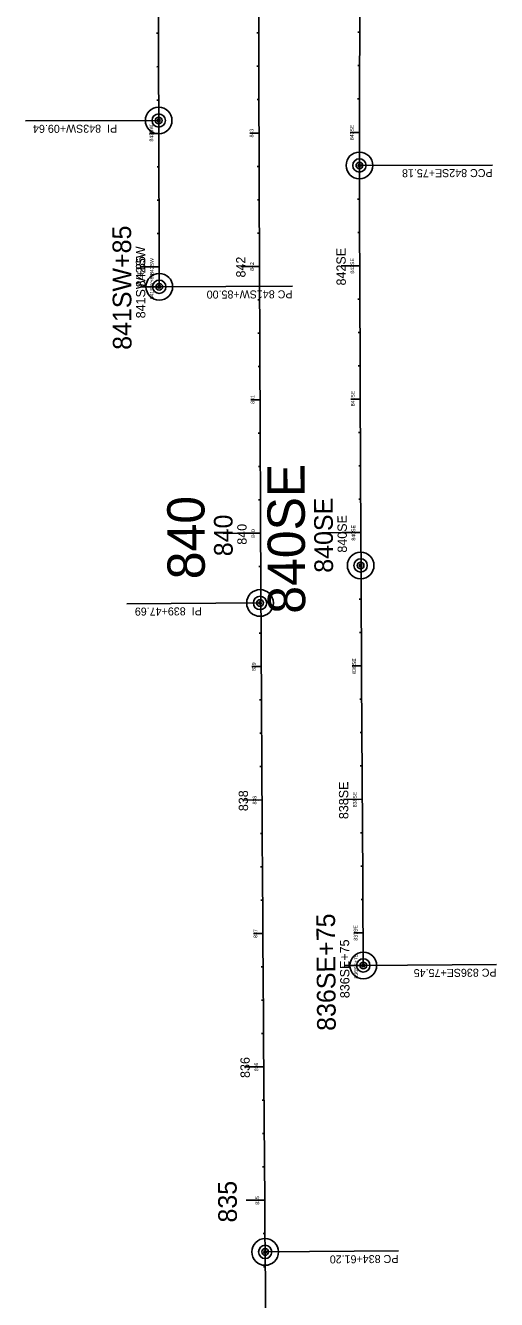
# Model space of a CAD drawing. Extents: x 536709 to 765910, y 180209 to 191282.
# Drawn here: x 593844 to 594197, y 182695 to 183650 of the extents above; entities that cross this region are included whole.
import ezdxf

# ---------------------------------------------------------------- set-up
doc = ezdxf.new("R2010")
doc.units = 0
for name, color, linetype in [('P_ALI_100', 7, 'Continuous'), ('P_ALI_100_Sta', 7, 'Continuous'), ('P_ALI_100_Tic', 7, 'Continuous'), ('P_ALI_100_TPI', 7, 'Continuous'), ('P_ALI_20', 7, 'Continuous'), ('P_ALI_200', 7, 'Continuous'), ('P_ALI_200_Sta', 7, 'Continuous'), ('P_ALI_200_Tic', 7, 'Continuous'), ('P_ALI_200_TPI', 7, 'Continuous'), ('P_ALI_20_Sta', 7, 'Continuous'), ('P_ALI_20_Tic', 7, 'Continuous'), ('P_ALI_20_TPI', 7, 'Continuous'), ('P_ALI_50', 7, 'Continuous'), ('P_ALI_50_CPIData', 7, 'Continuous'), ('P_ALI_50_PIData', 7, 'Continuous'), ('P_ALI_50_Sta', 7, 'Continuous'), ('P_ALI_50_Tic', 7, 'Continuous'), ('P_ALI_50_TPI', 7, 'Continuous')]:
    doc.layers.add(name, color=color, linetype=linetype)

msp = doc.modelspace()

# ---------------------------------------------------------------- linework, layer by layer
at = {"layer": 'P_ALI_100'}
msp.add_line((594043.57, 180219.08), (594023.71, 182730.2), dxfattribs=at)
for centre, radius, start, end in [((602094.41, 183570.03), 8000, 177.280358, 180.181641), ((765899.68, 184089.33), 171956.59, 180.1287302, 180.211791), ((765899.68, 184089.33), 171881.34, 180.1287302, 180.4530652), ((765899.68, 184089.33), 171806.09, 180.1816411, 180.381647)]:
    msp.add_arc(centre, radius, start, end, dxfattribs=at)
at = {"layer": 'P_ALI_100_Tic'}
for points in [[(594012.13, 183568.96), (594019.13, 183568.98)], [(594087.41, 183569.48), (594094.41, 183569.48)], [(593936.88, 183568.68), (593943.88, 183568.71)], [(593937.21, 183468.68), (593944.21, 183468.71)], [(594012.46, 183468.96), (594019.46, 183468.98)], [(594087.71, 183469.46), (594094.71, 183469.49)], [(593930.26, 183453.65), (593944.26, 183453.71)], [(593937.26, 183453.68), (593944.26, 183453.71)], [(594012.85, 183368.96), (594019.85, 183368.98)], [(594088.1, 183369.46), (594095.1, 183369.49)], [(594006.3, 183268.92), (594020.3, 183268.99)], [(594081.55, 183269.42), (594095.54, 183269.49)], [(594013.8, 183168.95), (594020.8, 183168.99)], [(594089.05, 183169.45), (594096.05, 183169.49)], [(594014.37, 183068.95), (594021.37, 183068.99)], [(594089.62, 183069.45), (594096.62, 183069.49)], [(594014.99, 182968.95), (594021.99, 182968.99)], [(594090.24, 182969.45), (594097.24, 182969.49)], [(594083.4, 182944.85), (594097.4, 182944.94)], [(594090.4, 182944.9), (594097.4, 182944.94)], [(594015.67, 182868.94), (594022.67, 182868.99)], [(594009.41, 182768.89), (594023.41, 182769)]]:
    msp.add_lwpolyline(points, dxfattribs=at)
at = {"layer": 'P_ALI_100_TPI'}
for centre in [(593943.8, 183578.35), (594094.45, 183544.67), (593944.26, 183453.71), (594095.4, 183244.8), (594019.87, 183216.67), (594097.4, 182944.94), (594023.71, 182730.2)]:
    msp.add_circle(centre, 5, dxfattribs=at)
at = {"layer": 'P_ALI_20'}
msp.add_line((594043.57, 180219.08), (594023.71, 182730.2), dxfattribs=at)
for centre, radius, start, end in [((602094.41, 183570.03), 8000, 177.280358, 180.181641), ((765899.68, 184089.33), 171956.59, 180.1287302, 180.211791), ((765899.68, 184089.33), 171881.34, 180.1287302, 180.4530652), ((765899.68, 184089.33), 171806.09, 180.1816411, 180.381647)]:
    msp.add_arc(centre, radius, start, end, dxfattribs=at)
at = {"layer": 'P_ALI_200'}
msp.add_line((594043.57, 180219.08), (594023.71, 182730.2), dxfattribs=at)
for centre, radius, start, end in [((602094.41, 183570.03), 8000, 177.280358, 180.181641), ((765899.68, 184089.33), 171956.59, 180.1287302, 180.211791), ((765899.68, 184089.33), 171881.34, 180.1287302, 180.4530652), ((765899.68, 184089.33), 171806.09, 180.1816411, 180.381647)]:
    msp.add_arc(centre, radius, start, end, dxfattribs=at)
at = {"layer": 'P_ALI_200_Tic'}
for points in [[(593930.21, 183468.66), (593944.21, 183468.71)], [(594005.46, 183468.93), (594019.46, 183468.98)], [(594080.71, 183469.43), (594094.71, 183469.49)], [(593992.3, 183268.85), (594020.3, 183268.99)], [(594067.55, 183269.35), (594095.54, 183269.49)], [(594007.37, 183068.91), (594021.37, 183068.99)], [(594082.62, 183069.41), (594096.62, 183069.49)], [(594008.67, 182868.89), (594022.67, 182868.99)]]:
    msp.add_lwpolyline(points, dxfattribs=at)
at = {"layer": 'P_ALI_200_TPI'}
for centre in [(593943.8, 183578.35), (594094.45, 183544.67), (593944.26, 183453.71), (594095.4, 183244.8), (594019.87, 183216.67), (594097.4, 182944.94), (594023.71, 182730.2)]:
    msp.add_circle(centre, 10, dxfattribs=at)
at = {"layer": 'P_ALI_20_Tic'}
for points in [[(593942.27, 183643.7), (593943.67, 183643.71)], [(594017.52, 183643.98), (594018.92, 183643.98)], [(594093.36, 183644.5), (594094.76, 183644.48)], [(593942.33, 183618.7), (593943.73, 183618.71)], [(594017.58, 183618.98), (594018.98, 183618.98)], [(594093.16, 183619.49), (594094.56, 183619.48)], [(593942.4, 183593.7), (593943.8, 183593.71)], [(594017.65, 183593.98), (594019.05, 183593.98)], [(594093.05, 183594.49), (594094.45, 183594.48)], [(594016.33, 183568.98), (594019.13, 183568.98)], [(594091.61, 183569.48), (594094.41, 183569.48)], [(593941.08, 183568.7), (593943.88, 183568.71)], [(593942.55, 183543.7), (593943.95, 183543.71)], [(594017.8, 183543.98), (594019.2, 183543.98)], [(594093.05, 183544.48), (594094.45, 183544.48)], [(593942.64, 183518.7), (593944.04, 183518.71)], [(594017.89, 183518.98), (594019.29, 183518.98)], [(594093.13, 183519.48), (594094.53, 183519.49)], [(593942.72, 183493.7), (593944.12, 183493.71)], [(594017.97, 183493.98), (594019.37, 183493.98)], [(594093.22, 183494.48), (594094.62, 183494.49)], [(593941.41, 183468.7), (593944.21, 183468.71)], [(594016.66, 183468.97), (594019.46, 183468.98)], [(594091.91, 183469.48), (594094.71, 183469.49)], [(593941.46, 183453.7), (593944.26, 183453.71)], [(593942.86, 183453.7), (593944.26, 183453.71)], [(594018.15, 183443.98), (594019.55, 183443.98)], [(594093.4, 183444.48), (594094.8, 183444.49)], [(594018.25, 183418.98), (594019.65, 183418.98)], [(594093.49, 183419.48), (594094.89, 183419.49)], [(594018.35, 183393.98), (594019.75, 183393.98)], [(594093.59, 183394.48), (594094.99, 183394.49)], [(594017.05, 183368.97), (594019.85, 183368.98)], [(594092.3, 183369.47), (594095.1, 183369.49)], [(594018.55, 183343.98), (594019.95, 183343.99)], [(594093.8, 183344.48), (594095.2, 183344.49)], [(594018.67, 183318.98), (594020.07, 183318.99)], [(594093.91, 183319.48), (594095.31, 183319.49)], [(594018.78, 183293.98), (594020.18, 183293.99)], [(594094.03, 183294.48), (594095.43, 183294.49)], [(594017.5, 183268.97), (594020.3, 183268.99)], [(594092.74, 183269.47), (594095.54, 183269.49)], [(594094.27, 183244.48), (594095.67, 183244.49)], [(594019.02, 183243.98), (594020.42, 183243.99)], [(594019.14, 183218.98), (594020.54, 183218.99)], [(594094.39, 183219.48), (594095.79, 183219.49)], [(594019.27, 183193.98), (594020.67, 183193.99)], [(594094.52, 183194.48), (594095.92, 183194.49)], [(594018, 183168.97), (594020.8, 183168.99)], [(594093.25, 183169.47), (594096.05, 183169.49)], [(594019.54, 183143.98), (594020.94, 183143.99)], [(594094.79, 183144.48), (594096.19, 183144.49)], [(594019.68, 183118.98), (594021.08, 183118.99)], [(594094.93, 183119.48), (594096.33, 183119.49)], [(594019.82, 183093.98), (594021.22, 183093.99)], [(594095.07, 183094.48), (594096.47, 183094.49)], [(594018.57, 183068.97), (594021.37, 183068.99)], [(594093.82, 183069.47), (594096.62, 183069.49)], [(594020.12, 183043.98), (594021.52, 183043.99)], [(594095.37, 183044.48), (594096.77, 183044.49)], [(594020.27, 183018.98), (594021.67, 183018.99)], [(594095.52, 183019.48), (594096.92, 183019.49)], [(594020.43, 182993.98), (594021.83, 182993.99)], [(594095.68, 182994.48), (594097.08, 182994.49)], [(594019.19, 182968.97), (594021.99, 182968.99)], [(594094.44, 182969.47), (594097.24, 182969.49)], [(594020.75, 182943.98), (594022.15, 182943.99)], [(594094.6, 182944.92), (594097.4, 182944.94)], [(594096, 182944.93), (594097.4, 182944.94)], [(594020.92, 182918.98), (594022.32, 182918.99)], [(594021.1, 182893.98), (594022.5, 182893.99)], [(594019.87, 182868.97), (594022.67, 182868.99)], [(594021.45, 182843.98), (594022.85, 182843.99)], [(594021.63, 182818.98), (594023.03, 182818.99)], [(594021.82, 182793.98), (594023.22, 182794)], [(594020.61, 182768.97), (594023.41, 182769)], [(594022.2, 182743.99), (594023.6, 182744)], [(594022.4, 182718.99), (594023.8, 182719)]]:
    msp.add_lwpolyline(points, dxfattribs=at)
at = {"layer": 'P_ALI_20_TPI'}
for centre in [(593943.8, 183578.35), (594094.45, 183544.67), (593944.26, 183453.71), (594095.4, 183244.8), (594019.87, 183216.67), (594097.4, 182944.94), (594023.71, 182730.2)]:
    msp.add_circle(centre, 1, dxfattribs=at)
at = {"layer": 'P_ALI_50'}
msp.add_line((594043.57, 180219.08), (594023.71, 182730.2), dxfattribs=at)
for centre, radius, start, end in [((602094.41, 183570.03), 8000, 177.280358, 180.181641), ((765899.68, 184089.33), 171956.59, 180.1287302, 180.211791), ((765899.68, 184089.33), 171881.34, 180.1287302, 180.4530652), ((765899.68, 184089.33), 171806.09, 180.1816411, 180.381647)]:
    msp.add_arc(centre, radius, start, end, dxfattribs=at)
at = {"layer": 'P_ALI_50_CPIData'}
for points in [[(593943.8, 183578.35), (593843.8, 183578.05)], [(594019.87, 183216.67), (593919.87, 183216.16)]]:
    msp.add_lwpolyline(points, dxfattribs=at)
at = {"layer": 'P_ALI_50_PIData'}
for points in [[(594094.45, 183544.67), (594194.45, 183544.99)], [(593944.26, 183453.71), (594044.26, 183454.08)], [(594097.4, 182944.94), (594197.4, 182945.61)], [(594023.71, 182730.2), (594123.71, 182730.99)]]:
    msp.add_lwpolyline(points, dxfattribs=at)
at = {"layer": 'P_ALI_50_Tic'}
for points in [[(594015.63, 183568.97), (594019.13, 183568.98)], [(594090.91, 183569.48), (594094.41, 183569.48)], [(593940.38, 183568.69), (593943.88, 183568.71)], [(593937.21, 183468.68), (593944.21, 183468.71)], [(594012.46, 183468.96), (594019.46, 183468.98)], [(594087.71, 183469.46), (594094.71, 183469.49)], [(593937.26, 183453.68), (593944.26, 183453.71)], [(593940.76, 183453.69), (593944.26, 183453.71)], [(594016.35, 183368.97), (594019.85, 183368.98)], [(594091.6, 183369.47), (594095.1, 183369.49)], [(594013.3, 183268.95), (594020.3, 183268.99)], [(594088.55, 183269.45), (594095.54, 183269.49)], [(594017.3, 183168.97), (594020.8, 183168.99)], [(594092.55, 183169.47), (594096.05, 183169.49)], [(594014.37, 183068.95), (594021.37, 183068.99)], [(594089.62, 183069.45), (594096.62, 183069.49)], [(594018.49, 182968.97), (594021.99, 182968.99)], [(594093.74, 182969.47), (594097.24, 182969.49)], [(594090.4, 182944.9), (594097.4, 182944.94)], [(594093.9, 182944.92), (594097.4, 182944.94)], [(594015.67, 182868.94), (594022.67, 182868.99)], [(594019.91, 182768.97), (594023.41, 182769)]]:
    msp.add_lwpolyline(points, dxfattribs=at)
at = {"layer": 'P_ALI_50_TPI'}
for centre in [(593943.8, 183578.35), (594094.45, 183544.67), (593944.26, 183453.71), (594095.4, 183244.8), (594019.87, 183216.67), (594097.4, 182944.94), (594023.71, 182730.2)]:
    msp.add_circle(centre, 2.5, dxfattribs=at)

# ---------------------------------------------------------------- texts
at = {"layer": 'P_ALI_100_Sta'}
for s, rotation, p in [('841SW+85', 90.21179, (593923.44, 183406.45)), ('840SE', 90.27341, (594074.69, 183239.35)), ('840', 90.27346, (593999.38, 183251.74)), ('836SE+75', 90.38165, (594076.73, 182895.97)), ('835', 90.44013, (594002.54, 182752.3))]:
    msp.add_text(s, height=14, rotation=rotation, dxfattribs=at).set_placement(p)
at = {"layer": 'P_ALI_200_Sta'}
for s, rotation, p in [('840SE', 90.27341, (594053.83, 183208.66)), ('840', 90.27346, (593978.46, 183234.5))]:
    msp.add_text(s, height=28, rotation=rotation, dxfattribs=at).set_placement(p)
at = {"layer": 'P_ALI_20_Sta'}
for s, rotation, p in [('843SW', 90.17347, (593939.7, 183562.55)), ('843', 90.17346, (594014.94, 183565.66)), ('843SE', 90.00391, (594090.21, 183563.59)), ('842SW', 90.20679, (593940.03, 183462.55)), ('842SE', 90.20671, (594090.53, 183463.57)), ('842', 90.20679, (594015.27, 183465.66)), ('841SW+85', 90.21179, (593940.1, 183444.25)), ('841', 90.24013, (594015.66, 183366.01)), ('841SE', 90.24006, (594090.92, 183364.14)), ('840SE', 90.27341, (594091.37, 183263.46)), ('840', 90.27346, (594016.11, 183265.54)), ('839', 90.30679, (594016.62, 183165.66)), ('839SE', 90.30676, (594091.88, 183163.55)), ('838SE', 90.34011, (594092.45, 183063.57)), ('838', 90.34013, (594017.19, 183065.66)), ('837', 90.37346, (594017.81, 182965.66)), ('837SE', 90.37346, (594093.08, 182963.57)), ('836SE+75', 90.38165, (594093.27, 182935.15)), ('836', 90.4068, (594018.49, 182865.66)), ('835', 90.44013, (594019.24, 182765.66))]:
    msp.add_text(s, height=2.8, rotation=rotation, dxfattribs=at).set_placement(p)
at = {"layer": 'P_ALI_50_CPIData'}
for s, rotation, p in [('PI  843SW+09.64', 180.17026, (593912.6, 183575.25)), ('PI  839+47.69', 180.2909, (593976.1, 183213.45))]:
    msp.add_text(s, height=6, rotation=rotation, dxfattribs=at).set_placement(p)
at = {"layer": 'P_ALI_50_PIData'}
for s, rotation, p in [('PCC 842SE+75.18', 180.18164, (594194.46, 183541.99)), ('PC 841SW+85.00', 180.21179, (594044.27, 183451.08)), ('PC 836SE+75.45', 180.38165, (594197.42, 182942.61)), ('PC 834+61.20', 180.45307, (594123.73, 182727.99))]:
    msp.add_text(s, height=6, rotation=rotation, dxfattribs=at).set_placement(p)
at = {"layer": 'P_ALI_50_Sta'}
for s, rotation, p in [('842SW', 90.20679, (593933.76, 183453.32)), ('841SW+85', 90.21179, (593933.85, 183430.08)), ('842', 90.20679, (594008.99, 183460.68)), ('842SE', 90.20671, (594084.26, 183454.7)), ('840', 90.27346, (594009.84, 183260.37)), ('840SE', 90.27341, (594085.12, 183254.42)), ('838SE', 90.34011, (594086.2, 183054.68)), ('838', 90.34013, (594010.92, 183060.66)), ('836SE+75', 90.38165, (594087.06, 182920.46)), ('836', 90.4068, (594012.23, 182860.65))]:
    msp.add_text(s, height=7, rotation=rotation, dxfattribs=at).set_placement(p)

doc.saveas('drawing.dxf')
